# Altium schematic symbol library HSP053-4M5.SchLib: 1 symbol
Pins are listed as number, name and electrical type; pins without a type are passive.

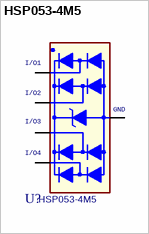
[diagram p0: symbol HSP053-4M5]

## HSP053-4M5
designator U?
footprint ST_QFN130x80x50-5L (Footprint not found)
pins: 1 I/O1, 2 GND, 3 I/O4, 4 I/O3, 5 I/O2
